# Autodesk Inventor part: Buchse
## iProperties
Created: 2007-11
Part Number: Buchse
Document SubType Name: Modeling
Designer: Benno
Manufacturer: Standard
Standards Organization: Custom
Author: Benno
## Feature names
1. Extrusion1
2. Bohrung1 [Hole]
